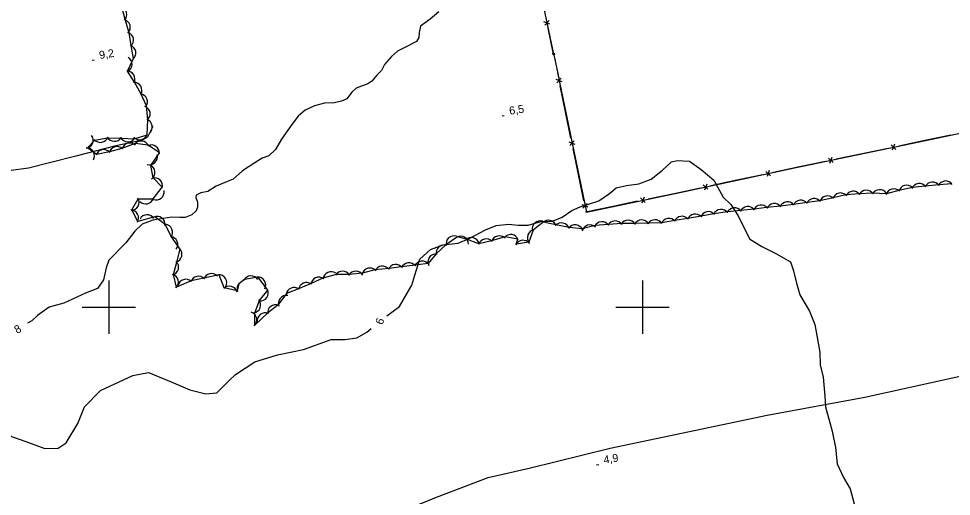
# Model space of a CAD drawing. Extents: x 643342 to 646936, y 5873857 to 5876103.
# Drawn here: x 644566.3 to 644915.8, y 5875329 to 5875508.2 of the extents above; entities that cross this region are included whole.
import ezdxf

# ---------------------------------------------------------------- set-up
doc = ezdxf.new("R2010")
doc.units = 0
for name, color, linetype in [('Niveau 2', 7, 'Continuous'), ('Niveau 22', 7, 'Continuous'), ('Niveau 23', 7, 'Continuous'), ('Niveau 3', 7, 'Continuous'), ('Niveau 37', 7, 'Continuous'), ('Niveau 44', 7, 'Continuous'), ('Niveau 61', 7, 'Continuous')]:
    doc.layers.add(name, color=color, linetype=linetype)

msp = doc.modelspace()

# ---------------------------------------------------------------- linework, layer by layer
at = {"layer": 'Niveau 2'}
for points in [[(644723.71, 5875510.77), (644720.47, 5875508.07), (644716.88, 5875505.34), (644716.37, 5875503.04), (644716.23, 5875501.12)], [(644716.23, 5875501.12), (644715.32, 5875499.66), (644711.22, 5875497.52), (644708.27, 5875496.02), (644706.01, 5875494.05), (644703.39, 5875491), (644702.17, 5875488.8), (644700.53, 5875486.95), (644698.59, 5875484.72), (644697.11, 5875483.71), (644692.74, 5875482.19), (644691.14, 5875480.63), (644689.21, 5875478.17), (644687.21, 5875477.22), (644684.58, 5875476.69), (644680.86, 5875476.52), (644677.16, 5875475.54), (644673.64, 5875473.92), (644671, 5875471.62), (644668.62, 5875468.47), (644664.76, 5875462.95), (644662.5, 5875459.1), (644660.04, 5875456.76), (644657.5, 5875455.83), (644654.74, 5875454.16), (644650.13, 5875451.15), (644646.63, 5875448.01), (644644.15, 5875447.02), (644640.28, 5875445.43), (644637.2, 5875443.44), (644634.5, 5875442.9), (644632.75, 5875442), (644632.65, 5875441.17), (644633.24, 5875439.32), (644633.23, 5875437.55), (644632.81, 5875436.11), (644631.17, 5875434.6), (644628.69, 5875433.67), (644626.65, 5875433.66), (644623.66, 5875433.73), (644620.44, 5875433.26), (644616.52, 5875432.66), (644612.57, 5875431.18), (644609.84, 5875428.52), (644606.4, 5875424.15), (644599.99, 5875417.68), (644598.99, 5875414.71), (644598.01, 5875410.21), (644595.8, 5875407), (644591.29, 5875405.23), (644583.22, 5875401.55), (644577.69, 5875399.97), (644573.36, 5875396.93), (644571.15, 5875394.9), (644569.54, 5875393.97)], [(644704.22, 5875396.78), (644709.02, 5875400.24), (644713.58, 5875408.19), (644714.74, 5875412.06), (644716.62, 5875418.06), (644720.6, 5875421.66), (644725.34, 5875423.33), (644730.94, 5875423.97), (644735.03, 5875425.7), (644741.19, 5875429.03), (644745.24, 5875430.58), (644749.85, 5875431.19), (644753.44, 5875430.81), (644757.17, 5875430.81), (644761.95, 5875432.07), (644766.36, 5875432.25), (644769.94, 5875433.81), (644773.56, 5875436.26), (644776.69, 5875437.67), (644783.7, 5875439.9), (644787.69, 5875442.62), (644790.12, 5875444.72), (644794.05, 5875445.61), (644798.64, 5875446.27), (644803.31, 5875448.05), (644807.53, 5875451.38), (644810.84, 5875454.56), (644813.06, 5875455.06), (644817.64, 5875454.72), (644822, 5875451.66), (644826.8, 5875447.65), (644830.2, 5875441.21), (644833.19, 5875438.55), (644835.87, 5875434.23), (644840.18, 5875425.59), (644844.81, 5875422.79), (644850.06, 5875420.17), (644855.54, 5875416.98), (644856.68, 5875413.57), (644857.76, 5875408.97), (644858.98, 5875404.68)], [(644858.98, 5875404.68), (644862.58, 5875398.56), (644864.63, 5875393.53), (644866.44, 5875383.08), (644866.59, 5875378.39), (644867.79, 5875373.75), (644868.36, 5875366.58), (644868.62, 5875362.62), (644871.17, 5875353.46), (644872.39, 5875347.35), (644873.03, 5875341.25), (644875.33, 5875336.06), (644877.82, 5875331.83), (644882.97, 5875312.58)], [(644560.02, 5875352.69), (644568.98, 5875349.64), (644576.02, 5875346.99), (644581.05, 5875347.11), (644584.02, 5875349.16), (644588.49, 5875356.41), (644590.96, 5875362.65), (644596.94, 5875368.74), (644609.06, 5875374.35), (644614.92, 5875375.48), (644623.44, 5875372.04), (644630.39, 5875369.03), (644636.38, 5875367.47), (644640.56, 5875367.86), (644645.15, 5875372.53), (644647.57, 5875374.76), (644654.78, 5875379.55), (644663.3, 5875382.11), (644673.05, 5875384.08), (644683.33, 5875387.86), (644688.52, 5875387.93), (644693.02, 5875388.52), (644696.73, 5875390.63), (644698.32, 5875392.01)]]:
    msp.add_lwpolyline(points, dxfattribs=at)
at = {"layer": 'Niveau 22'}
for points in [[(644616.54, 5875467.73), (644614.58, 5875463.79), (644612.58, 5875462.67), (644602.17, 5875460.42), (644587.7, 5875456.62), (644569.89, 5875452.16), (644562.63, 5875451.14)], [(644607.99, 5875276.54), (644615.34, 5875282.58), (644626.17, 5875289.28), (644635.97, 5875293.95), (644659.53, 5875302.81), (644722.84, 5875328.77), (644742.2, 5875336.13), (644757.56, 5875339.67), (644787.87, 5875347.1), (644846.76, 5875359.49), (644883.37, 5875366.24), (644949.1, 5875380.73), (645027.75, 5875398.1), (645075.65, 5875409.44), (645188.89, 5875433.56), (645246.8, 5875436.74), (645254.39, 5875435.12), (645258.48, 5875433.17), (645290.98, 5875420.13), (645338.2, 5875400.85), (645403.78, 5875377.34), (645494.14, 5875342.72), (645576.71, 5875308.93), (645614.3, 5875294.03)]]:
    msp.add_lwpolyline(points, dxfattribs=at)
at = {"layer": 'Niveau 23'}
msp.add_line((644766.77, 5875494.67), (644768.62, 5875485.86), dxfattribs=at)
for points in [[(644766.57, 5875495.65), (644766.67, 5875495.16), (644766.92, 5875495.21), (644767.03, 5875494.72), (644766.54, 5875494.62), (644766.43, 5875495.11), (644766.67, 5875495.16)], [(644766.88, 5875495.14), (644766.98, 5875494.75), (644766.88, 5875494.73), (644766.78, 5875495.12), (644766.68, 5875495.1), (644766.76, 5875494.71), (644766.69, 5875494.69), (644766.58, 5875495.08), (644766.51, 5875495.06), (644766.58, 5875494.69)]]:
    msp.add_lwpolyline(points, dxfattribs=at)
at = {"layer": 'Niveau 3'}
for p, q in [((644593.82, 5875492.62), (644594.61, 5875492.74)), ((644747.46, 5875471.73), (644748.25, 5875471.85)), ((644782.82, 5875340.86), (644783.61, 5875340.99))]:
    msp.add_line(p, q, dxfattribs=at)
at = {"layer": 'Niveau 37'}
for points in [[(645117.57, 5875650.61), (645049.07, 5875635.9), (644963.02, 5875617.79), (644871.7, 5875598.49), (644797.33, 5875582.76), (644750.3, 5875572.83), (644759.41, 5875529.24), (644766.72, 5875494.89)], [(644763.38, 5875505.79), (644765.07, 5875507.48)], [(644765.34, 5875506.2), (644763.11, 5875507.06)], [(644766.72, 5875494.89), (644764.64, 5875504.67)], [(644768.14, 5875488.02), (644778.99, 5875435.69), (644814.06, 5875443), (644857.04, 5875452.21), (644903.75, 5875462.01), (644955.79, 5875472.98), (645002.82, 5875483.14), (645067.74, 5875496.59), (645117.19, 5875506.96)], [(644769.88, 5875484.56), (644767.65, 5875485.42)], [(644767.92, 5875484.15), (644769.61, 5875485.83)], [(644771.2, 5875473.23), (644769.17, 5875483.02)], [(644773.23, 5875463.44), (644771.2, 5875473.23)], [(644774.75, 5875461.06), (644772.53, 5875461.93)], [(644772.79, 5875460.65), (644774.48, 5875462.33)], [(644905.84, 5875462.45), (644896.05, 5875460.39)], [(644915.62, 5875464.51), (644905.84, 5875462.45)], [(644776.07, 5875449.73), (644774.04, 5875459.52)], [(644892.14, 5875459.57), (644882.35, 5875457.52)], [(644894.93, 5875459.14), (644893.24, 5875460.83)], [(644894.52, 5875461.09), (644893.65, 5875458.87)], [(644871.44, 5875454.21), (644869.75, 5875455.9)], [(644871.03, 5875456.17), (644870.17, 5875453.94)], [(644882.35, 5875457.52), (644872.56, 5875455.47)], [(644858.86, 5875452.6), (644849.08, 5875450.51)], [(644868.65, 5875454.65), (644858.86, 5875452.59)], [(644778.1, 5875439.94), (644776.07, 5875449.73)], [(644845.17, 5875449.67), (644835.4, 5875447.57)], [(644847.96, 5875449.24), (644846.27, 5875450.93)], [(644847.54, 5875451.2), (644846.69, 5875448.97)], [(644821.71, 5875444.64), (644811.93, 5875442.54)], [(644824.5, 5875444.21), (644822.81, 5875445.89)], [(644824.08, 5875446.17), (644823.23, 5875443.94)], [(644835.4, 5875447.57), (644825.62, 5875445.47)], [(644801.01, 5875439.26), (644799.33, 5875440.95)], [(644800.6, 5875441.21), (644799.74, 5875438.99)], [(644811.93, 5875442.55), (644802.14, 5875440.51)], [(644779.62, 5875437.56), (644777.4, 5875438.43)], [(644777.66, 5875437.16), (644779.35, 5875438.83)], [(644788.43, 5875437.65), (644778.64, 5875435.61)], [(644798.22, 5875439.7), (644788.43, 5875437.65)]]:
    msp.add_lwpolyline(points, dxfattribs=at)
at = {"layer": 'Niveau 44'}
for points in [[(644648.2, 5875406.08), (644643.33, 5875407.21), (644641.44, 5875412.17), (644635.64, 5875410.83), (644630.88, 5875409.84), (644625.41, 5875407.5), (644624.26, 5875412.21), (644625.54, 5875416.9), (644626.76, 5875421.75), (644623.58, 5875426.43), (644621.12, 5875430.99), (644617.24, 5875433.91), (644610.89, 5875432.19), (644608.61, 5875436.47), (644611.06, 5875440.63), (644616.61, 5875440.59), (644620.06, 5875445), (644616.72, 5875448.52), (644615.84, 5875453.12), (644619.01, 5875457.91), (644614.77, 5875460.79), (644609.96, 5875461.39), (644604.93, 5875459.56), (644600.26, 5875458.24), (644595.37, 5875457.27), (644592, 5875459.74), (644594.83, 5875462.61), (644599.6, 5875463.54), (644604.67, 5875463.33), (644609.52, 5875463.11), (644614.42, 5875464.65), (644614.69, 5875470.24), (644614.14, 5875475.47), (644612.18, 5875479.92), (644609.61, 5875484.41), (644607.06, 5875488.53), (644609.32, 5875493.22), (644608.46, 5875498.15), (644607.62, 5875502.93), (644606.14, 5875507.89), (644604.91, 5875512.59)], [(644915.94, 5875446.3), (644911.1, 5875445.9), (644905.97, 5875445.43), (644901.15, 5875444.85), (644896.09, 5875443.75), (644891.42, 5875442.45), (644886.26, 5875442.71), (644881.41, 5875442.5), (644876.23, 5875442.08), (644871.49, 5875441.02), (644866.5, 5875439.85), (644861.69, 5875439.22), (644856.59, 5875438.56), (644851.77, 5875437.93), (644846.66, 5875437.35), (644841.84, 5875436.79), (644836.73, 5875436.25), (644831.9, 5875435.72), (644826.79, 5875434.99), (644822.01, 5875434.14), (644816.96, 5875433.21), (644812.16, 5875432.45), (644807.12, 5875431.59), (644802.27, 5875431.51), (644797.12, 5875431.43), (644792.27, 5875431.35), (644787.13, 5875430.95), (644782.28, 5875430.66), (644777.41, 5875429.39), (644772.58, 5875429.9), (644767.56, 5875430.86), (644762.8, 5875431.84), (644759.02, 5875428.94), (644757.41, 5875424.36), (644752.64, 5875423.64), (644753.35, 5875425.56), (644748.57, 5875426.4), (644743.46, 5875424.9), (644738.74, 5875423.78), (644734.07, 5875425.46), (644730.67, 5875426.41), (644726.32, 5875423.32), (644722.75, 5875420.03), (644719.67, 5875416.34), (644714.86, 5875415.73), (644709.75, 5875415.09), (644704.94, 5875414.49), (644699.75, 5875414.04), (644695.08, 5875412.74), (644690.06, 5875412.28), (644685.21, 5875412.3), (644680.26, 5875410.84), (644675.82, 5875408.88), (644671.07, 5875406.93), (644666.57, 5875405.12), (644663.42, 5875400.76), (644659.57, 5875397.81), (644654.77, 5875393.26), (644654.71, 5875397.92), (644656.45, 5875402.45), (644659.61, 5875406.32), (644656.01, 5875411.3), (644650.83, 5875410.35), (644648.75, 5875408.74), (644648.2, 5875406.08)]]:
    msp.add_lwpolyline(points, dxfattribs=at)
for centre, start, end in [((644603.82, 5875509.79), 314.7226, 74.7005), ((644603.82, 5875509.79), 314.7226, 74.7005), ((644603.82, 5875509.79), 314.7226, 74.7005), ((644605.09, 5875504.96), 314.7226, 74.7005), ((644605.09, 5875504.96), 314.7226, 74.7005), ((644605.09, 5875504.96), 314.7226, 74.7005), ((644606.3, 5875500.24), 309.9332, 69.9112), ((644606.3, 5875500.24), 309.9332, 69.9112), ((644606.3, 5875500.24), 309.9332, 69.9112), ((644607.16, 5875495.31), 309.9332, 69.9112), ((644607.16, 5875495.31), 309.9332, 69.9112), ((644607.16, 5875495.31), 309.9332, 69.9112), ((644605.74, 5875491.09), 299.216, 59.1939), ((644605.74, 5875491.09), 299.216, 59.1939), ((644605.74, 5875491.09), 299.216, 59.1939), ((644606.84, 5875485.54), 331.7952, 91.7731), ((644606.84, 5875485.54), 331.7952, 91.7731), ((644606.84, 5875485.54), 331.7952, 91.7731), ((644609.47, 5875481.29), 331.7952, 91.7731), ((644609.47, 5875481.29), 331.7952, 91.7731), ((644609.47, 5875481.29), 331.7952, 91.7731), ((644611.55, 5875476.99), 323.71, 83.688), ((644611.55, 5875476.99), 323.71, 83.688), ((644611.55, 5875476.99), 323.71, 83.688), ((644612.53, 5875472.49), 309.4482, 69.4261), ((644612.53, 5875472.49), 309.4482, 69.4261), ((644612.53, 5875472.49), 309.4482, 69.4261), ((644613.35, 5875467.56), 309.4482, 69.4261), ((644613.35, 5875467.56), 309.4482, 69.4261), ((644613.35, 5875467.56), 309.4482, 69.4261), ((644591.21, 5875462.55), 276.8837, 36.8616), ((644591.21, 5875462.55), 276.8837, 36.8616), ((644591.21, 5875462.55), 276.8837, 36.8616), ((644596.88, 5875464.8), 221.0251, 341.0031), ((644596.88, 5875464.8), 221.0251, 341.0031), ((644596.88, 5875464.8), 221.0251, 341.0031), ((644602.18, 5875465.21), 207.4384, 327.4164), ((644602.18, 5875465.21), 207.4384, 327.4164), ((644602.18, 5875465.21), 207.4384, 327.4164), ((644607.18, 5875464.98), 207.4384, 327.4164), ((644607.18, 5875464.98), 207.4384, 327.4164), ((644607.18, 5875464.98), 207.4384, 327.4164), ((644611.65, 5875465.8), 223.4609, 343.4389), ((644611.65, 5875465.8), 223.4609, 343.4389), ((644611.65, 5875465.8), 223.4609, 343.4389), ((644612.15, 5875459.34), 22.8789, 142.8568), ((644612.15, 5875459.34), 22.8789, 142.8568), ((644612.15, 5875459.34), 22.8789, 142.8568), ((644591.67, 5875456.76), 329.6868, 89.6647), ((644591.67, 5875456.76), 329.6868, 89.6647), ((644591.67, 5875456.76), 329.6868, 89.6647), ((644598.12, 5875456.08), 42.5649, 162.5429), ((644598.12, 5875456.08), 42.5649, 162.5429), ((644598.12, 5875456.08), 42.5649, 162.5429), ((644603.08, 5875457.2), 45.787, 165.7649), ((644603.08, 5875457.2), 45.787, 165.7649), ((644603.08, 5875457.2), 45.787, 165.7649), ((644607.89, 5875458.56), 45.787, 165.7649), ((644607.89, 5875458.56), 45.787, 165.7649), ((644607.89, 5875458.56), 45.787, 165.7649), ((644616.01, 5875457.84), 355.3551, 115.3331), ((644616.01, 5875457.84), 355.3551, 115.3331), ((644616.01, 5875457.84), 355.3551, 115.3331), ((644615.25, 5875456.38), 253.8605, 13.8384), ((644615.25, 5875456.38), 253.8605, 13.8384), ((644615.25, 5875456.38), 253.8605, 13.8384), ((644614.31, 5875450.54), 305.3868, 65.3647), ((644614.31, 5875450.54), 305.3868, 65.3647), ((644614.31, 5875450.54), 305.3868, 65.3647), ((644617.11, 5875445.54), 343.602, 103.58), ((644617.11, 5875445.54), 343.602, 103.58), ((644617.11, 5875445.54), 343.602, 103.58), ((644894.23, 5875441.4), 45.621, 165.5989), ((644894.23, 5875441.4), 45.621, 165.5989), ((644894.23, 5875441.4), 45.621, 165.5989), ((644899.05, 5875442.75), 45.621, 165.5989), ((644899.05, 5875442.75), 45.621, 165.5989), ((644899.05, 5875442.75), 45.621, 165.5989), ((644903.77, 5875443.39), 36.921, 156.899), ((644903.77, 5875443.39), 36.921, 156.899), ((644903.77, 5875443.39), 36.921, 156.899), ((644908.68, 5875443.94), 34.6345, 154.6125), ((644908.68, 5875443.94), 34.6345, 154.6125), ((644908.68, 5875443.94), 34.6345, 154.6125), ((644913.66, 5875444.34), 34.6345, 154.6125), ((644913.66, 5875444.34), 34.6345, 154.6125), ((644913.66, 5875444.34), 34.6345, 154.6125), ((644608.36, 5875439.32), 271.8257, 31.8036), ((644608.36, 5875439.32), 271.8257, 31.8036), ((644608.36, 5875439.32), 271.8257, 31.8036), ((644613.82, 5875441.72), 223.9676, 343.9455), ((644613.82, 5875441.72), 223.9676, 343.9455), ((644613.82, 5875441.72), 223.9676, 343.9455), ((644617.79, 5875443.24), 249.1758, 9.1537), ((644617.79, 5875443.24), 249.1758, 9.1537), ((644617.79, 5875443.24), 249.1758, 9.1537), ((644869.37, 5875438.74), 42.591, 162.5689), ((644869.37, 5875438.74), 42.591, 162.5689), ((644869.37, 5875438.74), 42.591, 162.5689), ((644874.25, 5875439.83), 42.591, 162.5689), ((644874.25, 5875439.83), 42.591, 162.5689), ((644874.25, 5875439.83), 42.591, 162.5689), ((644879, 5875440.5), 35.3154, 155.2933), ((644879, 5875440.5), 35.3154, 155.2933), ((644879, 5875440.5), 35.3154, 155.2933), ((644883.91, 5875440.84), 32.5371, 152.515), ((644883.91, 5875440.84), 32.5371, 152.515), ((644883.91, 5875440.84), 32.5371, 152.515), ((644888.91, 5875441.06), 32.5371, 152.515), ((644888.91, 5875441.06), 32.5371, 152.515), ((644888.91, 5875441.06), 32.5371, 152.515), ((644839.48, 5875434.77), 36.2345, 156.2124), ((644839.48, 5875434.77), 36.2345, 156.2124), ((644839.48, 5875434.77), 36.2345, 156.2124), ((644844.46, 5875435.32), 36.6932, 156.6711), ((644844.46, 5875435.32), 36.6932, 156.6711), ((644844.46, 5875435.32), 36.6932, 156.6711), ((644849.42, 5875435.9), 36.6932, 156.6711), ((644849.42, 5875435.9), 36.6932, 156.6711), ((644849.42, 5875435.9), 36.6932, 156.6711), ((644854.41, 5875436.49), 37.4574, 157.4353), ((644854.41, 5875436.49), 37.4574, 157.4353), ((644854.41, 5875436.49), 37.4574, 157.4353), ((644859.37, 5875437.14), 37.4574, 157.4353), ((644859.37, 5875437.14), 37.4574, 157.4353), ((644859.37, 5875437.14), 37.4574, 157.4353), ((644864.33, 5875437.79), 37.4574, 157.4353), ((644864.33, 5875437.79), 37.4574, 157.4353), ((644864.33, 5875437.79), 37.4574, 157.4353), ((644608.19, 5875433.5), 328.0845, 88.0625), ((644608.19, 5875433.5), 328.0845, 88.0625), ((644608.19, 5875433.5), 328.0845, 88.0625), ((644614.41, 5875431.65), 31.8154, 151.7933), ((644614.41, 5875431.65), 31.8154, 151.7933), ((644614.41, 5875431.65), 31.8154, 151.7933), ((644618.12, 5875431.04), 352.9845, 112.9625), ((644618.12, 5875431.04), 352.9845, 112.9625), ((644618.12, 5875431.04), 352.9845, 112.9625), ((644814.84, 5875431.09), 39.0179, 158.9958), ((644814.84, 5875431.09), 39.0179, 158.9958), ((644814.84, 5875431.09), 39.0179, 158.9958), ((644819.79, 5875431.95), 40.1232, 160.1012), ((644819.79, 5875431.95), 40.1232, 160.1012), ((644819.79, 5875431.95), 40.1232, 160.1012), ((644824.71, 5875432.83), 40.1232, 160.1012), ((644824.71, 5875432.83), 40.1232, 160.1012), ((644824.71, 5875432.83), 40.1232, 160.1012), ((644829.53, 5875433.69), 36.2345, 156.2124), ((644829.53, 5875433.69), 36.2345, 156.2124), ((644829.53, 5875433.69), 36.2345, 156.2124), ((644834.51, 5875434.23), 36.2345, 156.2124), ((644834.51, 5875434.23), 36.2345, 156.2124), ((644834.51, 5875434.23), 36.2345, 156.2124), ((644620.95, 5875428.11), 322.9553, 82.9333), ((644620.95, 5875428.11), 322.9553, 82.9333), ((644620.95, 5875428.11), 322.9553, 82.9333), ((644761.73, 5875429.34), 72.3929, 192.3708), ((644761.73, 5875429.34), 72.3929, 192.3708), ((644761.73, 5875429.34), 72.3929, 192.3708), ((644764.82, 5875429.62), 18.4357, 138.4136), ((644764.82, 5875429.62), 18.4357, 138.4136), ((644764.82, 5875429.62), 18.4357, 138.4136), ((644769.72, 5875428.62), 18.4357, 138.4136), ((644769.72, 5875428.62), 18.4357, 138.4136), ((644769.72, 5875428.62), 18.4357, 138.4136), ((644774.81, 5875427.89), 23.9222, 143.9001), ((644774.81, 5875427.89), 23.9222, 143.9001), ((644774.81, 5875427.89), 23.9222, 143.9001), ((644780.34, 5875427.86), 46.975, 166.9529), ((644780.34, 5875427.86), 46.975, 166.9529), ((644780.34, 5875427.86), 46.975, 166.9529), ((644784.81, 5875429.05), 33.4344, 153.4123), ((644784.81, 5875429.05), 33.4344, 153.4123), ((644784.81, 5875429.05), 33.4344, 153.4123), ((644789.8, 5875429.34), 33.4344, 153.4123), ((644789.8, 5875429.34), 33.4344, 153.4123), ((644789.8, 5875429.34), 33.4344, 153.4123), ((644794.73, 5875429.63), 30.9249, 150.9028), ((644794.73, 5875429.63), 30.9249, 150.9028), ((644794.73, 5875429.63), 30.9249, 150.9028), ((644799.72, 5875429.71), 30.9249, 150.9028), ((644799.72, 5875429.71), 30.9249, 150.9028), ((644799.72, 5875429.71), 30.9249, 150.9028), ((644804.72, 5875429.79), 30.9249, 150.9028), ((644804.72, 5875429.79), 30.9249, 150.9028), ((644804.72, 5875429.79), 30.9249, 150.9028), ((644809.9, 5875430.31), 39.0179, 158.9958), ((644809.9, 5875430.31), 39.0179, 158.9958), ((644809.9, 5875430.31), 39.0179, 158.9958), ((644750.66, 5875424.24), 20.1336, 140.1116), ((644750.66, 5875424.24), 20.1336, 140.1116), ((644750.66, 5875424.24), 20.1336, 140.1116), ((644759.88, 5875426.07), 100.5614, 220.5393), ((644759.88, 5875426.07), 100.5614, 220.5393), ((644759.88, 5875426.07), 100.5614, 220.5393), ((644622.9, 5875423.51), 322.9553, 82.9333), ((644622.9, 5875423.51), 322.9553, 82.9333), ((644622.9, 5875423.51), 322.9553, 82.9333), ((644729.41, 5875423.76), 72.5803, 192.5582), ((644729.41, 5875423.76), 72.5803, 192.5582), ((644729.41, 5875423.76), 72.5803, 192.5582), ((644731.83, 5875423.64), 358.7622, 118.7401), ((644731.83, 5875423.64), 358.7622, 118.7401), ((644731.83, 5875423.64), 358.7622, 118.7401), ((644735.92, 5875423.1), 14.1471, 134.125), ((644735.92, 5875423.1), 14.1471, 134.125), ((644735.92, 5875423.1), 14.1471, 134.125), ((644741.5, 5875422.62), 43.2342, 163.2122), ((644741.5, 5875422.62), 43.2342, 163.2122), ((644741.5, 5875422.62), 43.2342, 163.2122), ((644746.37, 5875423.77), 43.2342, 163.2122), ((644746.37, 5875423.77), 43.2342, 163.2122), ((644746.37, 5875423.77), 43.2342, 163.2122), ((644755.22, 5875422.1), 35.3204, 155.2984), ((644755.22, 5875422.1), 35.3204, 155.2984), ((644755.22, 5875422.1), 35.3204, 155.2984), ((644624.46, 5875419.83), 285.8173, 45.7953), ((644624.46, 5875419.83), 285.8173, 45.7953), ((644624.46, 5875419.83), 285.8173, 45.7953), ((644722.64, 5875416.97), 86.6591, 206.6371), ((644722.64, 5875416.97), 86.6591, 206.6371), ((644722.64, 5875416.97), 86.6591, 206.6371), ((644725.73, 5875420.38), 72.5803, 192.5582), ((644725.73, 5875420.38), 72.5803, 192.5582), ((644725.73, 5875420.38), 72.5803, 192.5582), ((644623.2, 5875415.02), 284.7724, 44.7504), ((644623.2, 5875415.02), 284.7724, 44.7504), ((644623.2, 5875415.02), 284.7724, 44.7504), ((644712.52, 5875413.66), 37.1555, 157.1335), ((644712.52, 5875413.66), 37.1555, 157.1335), ((644712.52, 5875413.66), 37.1555, 157.1335), ((644717.49, 5875414.28), 37.1555, 157.1335), ((644717.49, 5875414.28), 37.1555, 157.1335), ((644717.49, 5875414.28), 37.1555, 157.1335), ((644683.33, 5875410.27), 53.8874, 173.8653), ((644683.33, 5875410.27), 53.8874, 173.8653), ((644683.33, 5875410.27), 53.8874, 173.8653), ((644687.63, 5875410.53), 29.8465, 149.8245), ((644687.63, 5875410.53), 29.8465, 149.8245), ((644687.63, 5875410.53), 29.8465, 149.8245), ((644692.63, 5875410.51), 29.8465, 149.8245), ((644692.63, 5875410.51), 29.8465, 149.8245), ((644692.63, 5875410.51), 29.8465, 149.8245), ((644697.88, 5875411.69), 45.4783, 165.4562), ((644697.88, 5875411.69), 45.4783, 165.4562), ((644697.88, 5875411.69), 45.4783, 165.4562), ((644702.6, 5875412.42), 37.1555, 157.1335), ((644702.6, 5875412.42), 37.1555, 157.1335), ((644702.6, 5875412.42), 37.1555, 157.1335), ((644707.56, 5875413.04), 37.1555, 157.1335), ((644707.56, 5875413.04), 37.1555, 157.1335), ((644707.56, 5875413.04), 37.1555, 157.1335), ((644623.11, 5875409.42), 314.2128, 74.1908), ((644623.11, 5875409.42), 314.2128, 74.1908), ((644623.11, 5875409.42), 314.2128, 74.1908), ((644628.93, 5875407.45), 47.9304, 167.9084), ((644628.93, 5875407.45), 47.9304, 167.9084), ((644628.93, 5875407.45), 47.9304, 167.9084), ((644633.62, 5875408.61), 41.7022, 161.6802), ((644633.62, 5875408.61), 41.7022, 161.6802), ((644633.62, 5875408.61), 41.7022, 161.6802), ((644638.51, 5875409.62), 41.7022, 161.6802), ((644638.51, 5875409.62), 41.7022, 161.6802), ((644638.51, 5875409.62), 41.7022, 161.6802), ((644641.25, 5875409.17), 332.378, 92.356), ((644641.25, 5875409.17), 332.378, 92.356), ((644641.25, 5875409.17), 332.378, 92.356), ((644653.36, 5875408.73), 33.1878, 153.1657), ((644653.36, 5875408.73), 33.1878, 153.1657), ((644653.36, 5875408.73), 33.1878, 153.1657), ((644655.83, 5875408.3), 332.6279, 92.6058), ((644655.83, 5875408.3), 332.6279, 92.6058), ((644655.83, 5875408.3), 332.6279, 92.6058), ((644678.76, 5875408.25), 53.8874, 173.8653), ((644678.76, 5875408.25), 53.8874, 173.8653), ((644678.76, 5875408.25), 53.8874, 173.8653), ((644645.18, 5875404.85), 14.1719, 134.1499), ((644645.18, 5875404.85), 14.1719, 134.1499), ((644645.18, 5875404.85), 14.1719, 134.1499), ((644651.09, 5875406.87), 135.3747, 200.5313), ((644651.09, 5875406.87), 135.3747, 200.5313), ((644651.09, 5875406.87), 135.3747, 200.5313), ((644656.78, 5875405.33), 265.4035, 25.3815), ((644656.78, 5875405.33), 265.4035, 25.3815), ((644656.78, 5875405.33), 265.4035, 25.3815), ((644669.47, 5875404.39), 51.775, 171.753), ((644669.47, 5875404.39), 51.775, 171.753), ((644669.47, 5875404.39), 51.775, 171.753), ((644674.12, 5875406.24), 51.775, 171.753), ((644674.12, 5875406.24), 51.775, 171.753), ((644674.12, 5875406.24), 51.775, 171.753), ((644653.93, 5875400.82), 278.97, 38.9479), ((644653.93, 5875400.82), 278.97, 38.9479), ((644653.93, 5875400.82), 278.97, 38.9479), ((644666.55, 5875401.37), 79.7024, 199.6803), ((644666.55, 5875401.37), 79.7024, 199.6803), ((644666.55, 5875401.37), 79.7024, 199.6803), ((644662.57, 5875397.89), 67.4625, 187.4405), ((644662.57, 5875397.89), 67.4625, 187.4405), ((644662.57, 5875397.89), 67.4625, 187.4405), ((644652.53, 5875395.25), 312.4726, 72.4505), ((644652.53, 5875395.25), 312.4726, 72.4505), ((644652.53, 5875395.25), 312.4726, 72.4505), ((644658.6, 5875394.85), 67.4625, 187.4405), ((644658.6, 5875394.85), 67.4625, 187.4405), ((644658.6, 5875394.85), 67.4625, 187.4405)]:
    msp.add_arc(centre, 3, start, end, dxfattribs=at)
at = {"layer": 'Niveau 61'}
for points in [[(644600, 5875410), (644600, 5875400), (644600, 5875390)], [(644800, 5875410), (644800, 5875400), (644800, 5875390)], [(644590, 5875400), (644600, 5875400), (644610, 5875400)], [(644790, 5875400), (644800, 5875400), (644810, 5875400)]]:
    msp.add_lwpolyline(points, dxfattribs=at)

# ---------------------------------------------------------------- texts
at = {"layer": 'Niveau 2'}
for s, rotation, p in [('6', 70.2935, (644702.62, 5875393.19)), ('8', 30.022, (644565.67, 5875389.93))]:
    msp.add_text(s, height=3, rotation=rotation, dxfattribs=at).set_placement(p)
at = {"layer": 'Niveau 3'}
for s, rotation, p in [('9,2  ', 8.9405, (644596.67, 5875493.03)), ('6,5  ', 8.941, (644750.32, 5875472.14)), ('4,9  ', 8.9405, (644785.67, 5875341.27))]:
    msp.add_text(s, height=3, rotation=rotation, dxfattribs=at).set_placement(p)

doc.saveas('drawing.dxf')
